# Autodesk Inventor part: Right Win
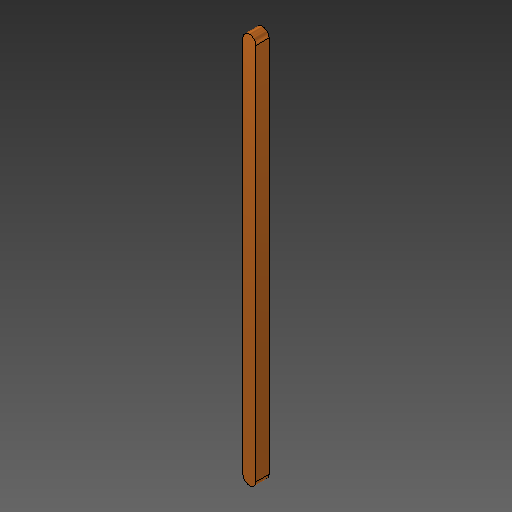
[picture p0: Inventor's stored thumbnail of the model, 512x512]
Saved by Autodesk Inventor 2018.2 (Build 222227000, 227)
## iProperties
Created: 2018-03
Part Number: Right Win
Material: Gold
Document SubType Name: Modeling
Designer: PeterMaxwell-Stewart
Mass: 70.8963 g
Surface Area: 29.7798 cm^2
Volume: 3.67338 cm^3
Density: 19.3 g/cm^3
Appearance: Metal 1600F Hot
Author: PeterMaxwell-Stewart
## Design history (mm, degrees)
derived "O's and X's.ipt"
feature "Right Win::O's and X's.ipt" dims "d0" = 10
tag "TaggingFeature1"
body "Solid1"
